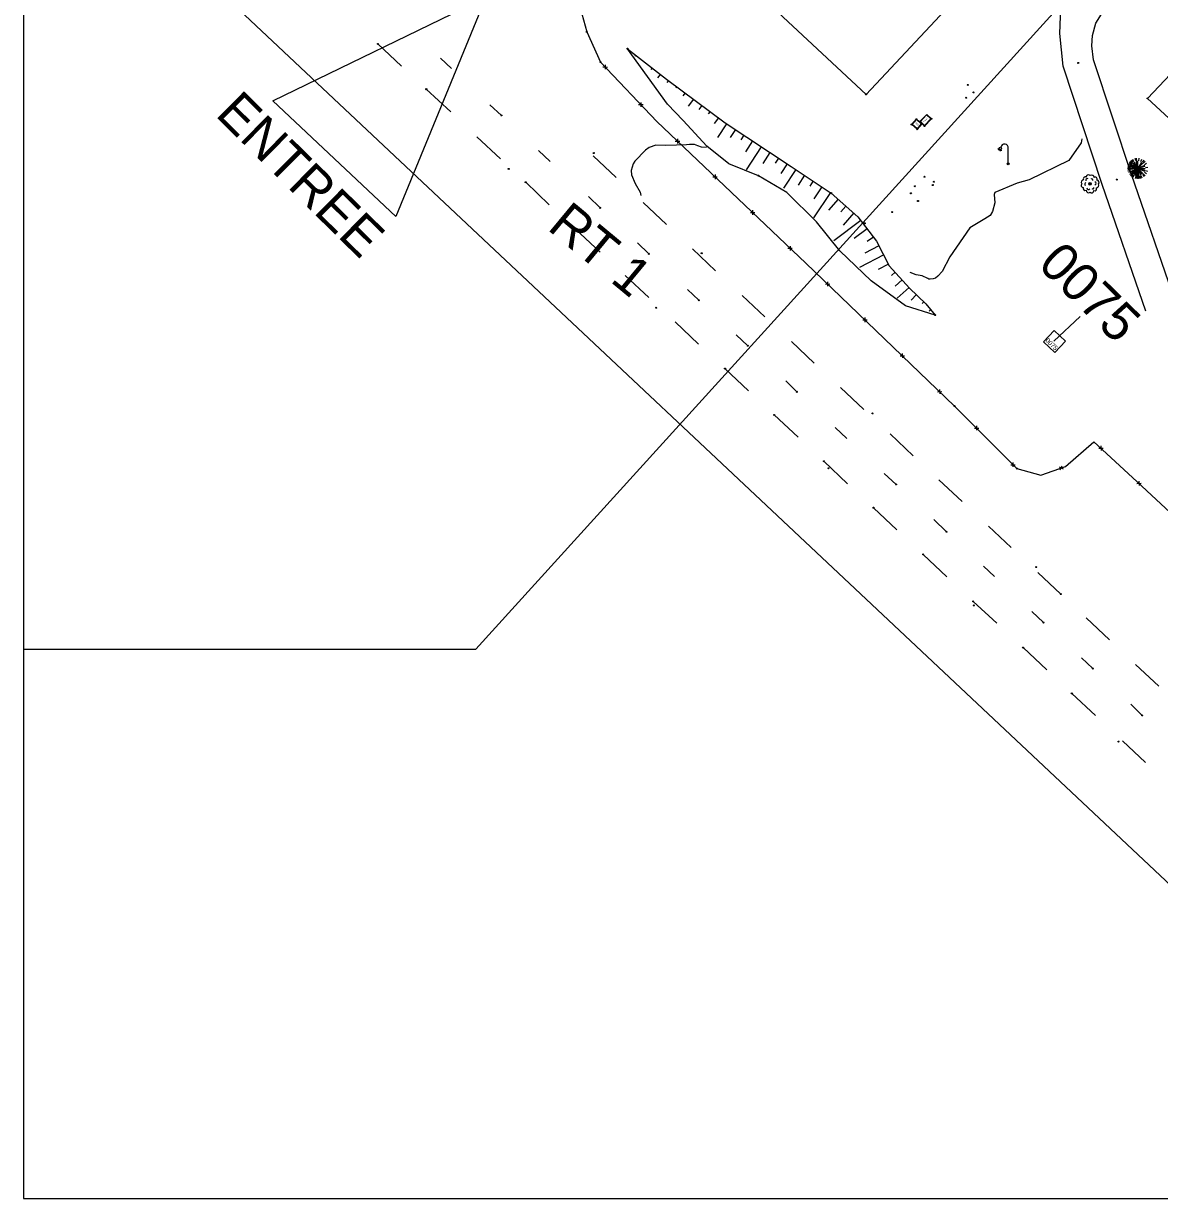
# Model space of a CAD drawing. Extents: x 344013 to 344423, y 298505 to 298795.
# Drawn here: x 344012.9 to 344122.6, y 298504.9 to 298618.3 of the extents above; entities that cross this region are included whole.
import ezdxf

# ---------------------------------------------------------------- set-up
doc = ezdxf.new("R2010")
doc.units = 0
for name, color, linetype in [('Default', 7, 'Continuous'), ('DH_CADRE -CARTOUCHE', 7, 'Continuous'), ('GO MUR EXTERIEUR', 7, 'Continuous'), ('IMM_VOIRIE VOIE FERREE', 7, 'Continuous'), ('PS_BOLT', 7, 'Continuous'), ('PS_CONST', 7, 'Continuous'), ('PS_DAWA', 7, 'Continuous'), ('PS_WELD', 7, 'Continuous'), ('RES_ELECTRICITE', 7, 'Continuous'), ('TOPO_COURBE NIVEAU', 7, 'Continuous'), ('TOPO_POINT', 7, 'Continuous'), ('TOPO_TALUS-TERRAIN NATUREL', 7, 'Continuous'), ('VOIRIE_BORDURE', 7, 'Continuous'), ('VOIRIE_ESPACE VERT', 7, 'Continuous')]:
    doc.layers.add(name, color=color, linetype=linetype)

# ---------------------------------------------------------------- blocks, each defined once
blk = doc.blocks.new('RES_ELECTRICITE')
at = {"layer": 'RES_ELECTRICITE'}
for points in [[(0, 0), (0, 1), (1, 1), (1, 0)], [(0.05, 0.05), (0.05, 0.95), (0.95, 0.95), (0.95, 0.05)]]:
    blk.add_lwpolyline(points, close=True, dxfattribs=at)
blk.add_text('EEC', height=0.2, dxfattribs=at).set_placement((0.24, 0.46))
blk = doc.blocks.new('EDF1')
at = {"layer": 'Default'}
for points in [[(-0.86, 1.46), (-0.98, 1.37)], [(-0.83, 1.42), (-0.93, 1.3)], [(-0.79, 1.4), (-0.86, 1.26)], [(-0.75, 1.39), (-0.78, 1.23)], [(-0.7, 1.4), (-0.68, 1.24)], [(0, 0.1), (0, 1.5)]]:
    blk.add_lwpolyline(points, dxfattribs=at)
for centre, radius in [((-0.75, 1.5), 0.112), ((0, 0), 0.1)]:
    blk.add_circle(centre, radius, dxfattribs=at)
blk.add_arc((-0.35, 1.55), 0.354, 351.8699, 171.8699, dxfattribs=at)
blk = doc.blocks.new('POINT_DISPLAY')
at = {"layer": 'Default'}
blk.add_circle((0, 0), 0.05, dxfattribs=at)
blk = doc.blocks.new('ARB1')
at = {"layer": 'Default'}
blk.add_circle((0, 0), 0.122, dxfattribs=at)
for centre, radius, start, end in [((-0.61, 0.14), 0.241, 88.4583, 215.1928), ((-0.47, 0.5), 0.183, 53.9554, 222.2066), ((-0.37, -0.02), 0.149, 103.7092, 242.3465), ((-0.28, 0.37), 0.134, 52.4396, 209.5496), ((-0.15, 0.66), 0.211, 43.6925, 183.5969), ((0.14, 0.61), 0.241, 358.4583, 125.1928), ((0.16, 0.38), 0.112, 330.5895, 133.7127), ((0.5, 0.47), 0.183, 325.1444, 131.0175), ((0.46, 0.05), 0.137, 276.6214, 88.967), ((0.61, -0.14), 0.241, 268.4583, 35.1928), ((0.66, 0.15), 0.211, 313.6925, 93.5969), ((-0.66, -0.15), 0.211, 133.6925, 273.5969), ((-0.48, -0.44), 0.19, 155.2243, 300.9377), ((-0.14, -0.61), 0.241, 178.4583, 305.1928), ((-0.16, -0.42), 0.148, 159.5371, 338.1663), ((0.15, -0.66), 0.211, 223.6925, 3.5969), ((0.27, -0.38), 0.112, 210.5895, 13.7127), ((0.45, -0.48), 0.188, 243.1323, 33.0297)]:
    blk.add_arc(centre, radius, start, end, dxfattribs=at)
blk = doc.blocks.new('ARB2')
at = {"layer": 'Default'}
for p, q in [((-0.73, 0), (-0.98, 0)), ((-0.72, 0.1), (-0.97, 0.13)), ((-0.71, 0.2), (-0.94, 0.26)), ((-0.67, 0.29), (-0.9, 0.38)), ((-0.63, 0.37), (-0.84, 0.5)), ((-0.58, 0.45), (-0.78, 0.6)), ((-0.51, 0.53), (-0.69, 0.7)), ((-0.44, 0.59), (-0.59, 0.79)), ((-0.36, 0.64), (-0.48, 0.86)), ((-0.18, 0.72), (-0.24, 0.96)), ((-0.09, 0.74), (-0.12, 0.98)), ((0.11, 0.74), (0.14, 0.98)), ((0.29, 0.68), (0.39, 0.91)), ((0.46, 0.59), (0.61, 0.79)), ((0.53, 0.53), (0.71, 0.7)), ((0.65, 0.37), (0.86, 0.5)), ((0.74, 0.1), (0.99, 0.13)), ((-0.72, -0.1), (-0.97, -0.13)), ((-0.71, -0.2), (-0.94, -0.26)), ((-0.67, -0.29), (-0.9, -0.38)), ((-0.58, -0.45), (-0.78, -0.6)), ((-0.51, -0.53), (-0.69, -0.7)), ((-0.44, -0.59), (-0.59, -0.79)), ((-0.36, -0.64), (-0.48, -0.86)), ((-0.18, -0.72), (-0.24, -0.96)), ((-0.09, -0.74), (-0.12, -0.98)), ((0.01, -0.74), (0.01, -0.99)), ((0.11, -0.74), (0.14, -0.98)), ((0.2, -0.72), (0.26, -0.96)), ((0.29, -0.69), (0.39, -0.92)), ((0.46, -0.59), (0.61, -0.79)), ((0.53, -0.53), (0.71, -0.7)), ((0.65, -0.37), (0.86, -0.5)), ((0.72, -0.2), (0.96, -0.26))]:
    blk.add_line(p, q, dxfattribs=at)
for points in [[(-0.69, 0.09), (0.01, 0), (-0.34, 0.61)], [(-0.49, -0.5), (0.01, 0), (-0.69, 0)], [(-0.64, -0.27), (0.01, 0), (-0.69, -0.09)], [(-0.49, 0.5), (0.01, 0), (-0.67, 0.18)], [(-0.42, 0.56), (0.01, 0), (-0.64, 0.27)], [(-0.17, 0.68), (0.01, 0), (-0.6, 0.35)], [(-0.17, -0.68), (0.01, 0), (-0.6, -0.35)], [(-0.54, -0.43), (0.01, 0), (-0.34, -0.61)], [(-0.08, -0.7), (0.01, 0), (-0.42, -0.56)], [(0.01, 0.01), (0.01, 0), (-0.08, 0.7)], [(0.01, -0.7), (0.01, 0), (0, 0)], [(0.36, 0.61), (0.01, 0), (0.01, 0.7)], [(0.66, 0.27), (0.01, 0), (0.51, 0.5)], [(0.69, 0.18), (0.01, 0), (0.71, 0)], [(0.44, -0.56), (0.01, 0), (0.66, -0.27)], [(0.51, -0.5), (0.01, 0), (0.69, -0.18)], [(0.1, -0.7), (0.01, 0), (0.28, -0.65)], [(0.02, 0), (0.01, 0), (0.01, -0.01)]]:
    blk.add_lwpolyline(points, dxfattribs=at)

msp = doc.modelspace()

# ---------------------------------------------------------------- linework, layer by layer
at = {"layer": 'DH_CADRE -CARTOUCHE'}
for points in [[(344012.91, 298504.88), (344422.91, 298504.88), (344422.91, 298791.88), (344012.91, 298791.88)], [(344113.5, 298587.61), (344112.41, 298588.64), (344111.38, 298587.55), (344112.47, 298586.52)]]:
    msp.add_lwpolyline(points, close=True, dxfattribs=at)
msp.add_lwpolyline([(344092.72, 298634.81), (344105.19, 298623.15), (344094.24, 298611.44), (344080.1, 298624.66), (344082.36, 298627.12), (344084.04, 298625.58), (344092.72, 298634.81)], dxfattribs=at)
at = {"layer": 'GO MUR EXTERIEUR'}
for points in [[(344092.72, 298634.81), (344105.19, 298623.15), (344094.24, 298611.44), (344080.1, 298624.66), (344082.36, 298627.12), (344084.04, 298625.58)], [(344036.98, 298610.8), (344057.54, 298620.81), (344048.84, 298599.66)]]:
    msp.add_lwpolyline(points, close=True, dxfattribs=at)
at = {"layer": 'IMM_VOIRIE VOIE FERREE'}
for points in [[(344047.12, 298616.31), (344049.39, 298614.15)], [(344054.22, 298613.94), (344053.16, 298614.92)], [(344051.79, 298611.94), (344054.15, 298609.75)], [(344059.04, 298609.41), (344057.93, 298610.43)], [(344056.67, 298607.35), (344058.95, 298605.23)], [(344063.76, 298604.96), (344062.62, 298606.03)], [(344070.12, 298603.4), (344067.9, 298605.51)], [(344061.38, 298602.96), (344063.66, 298600.78)], [(344068.56, 298600.49), (344067.43, 298601.57)], [(344074.96, 298598.89), (344072.72, 298601)], [(344066.19, 298598.43), (344068.56, 298596.22)], [(344073.27, 298596.05), (344072.18, 298597.11)], [(344079.7, 298594.42), (344077.49, 298596.53)], [(344070.99, 298593.96), (344073.28, 298591.82)], [(344078.09, 298591.57), (344076.99, 298592.6)], [(344084.46, 298589.96), (344082.27, 298592.04)], [(344075.8, 298589.5), (344078.06, 298587.34)], [(344082.82, 298587.18), (344081.7, 298588.24)], [(344089.22, 298585.5), (344087.04, 298587.58)], [(344080.62, 298584.97), (344082.88, 298582.83)], [(344087.55, 298582.73), (344086.49, 298583.78)], [(344094.01, 298581.04), (344091.78, 298583.16)], [(344085.36, 298580.5), (344087.68, 298578.35)], [(344092.38, 298578.22), (344091.26, 298579.28)], [(344098.79, 298576.56), (344096.56, 298578.67)], [(344090.17, 298576.03), (344092.44, 298573.86)], [(344097.14, 298573.79), (344096, 298574.84)], [(344103.53, 298572.13), (344101.27, 298574.23)], [(344094.95, 298571.55), (344097.21, 298569.4)], [(344102.01, 298569.22), (344100.77, 298570.4)], [(344108.26, 298567.71), (344106.06, 298569.78)], [(344099.76, 298567.04), (344102.04, 298564.87)], [(344106.63, 298564.9), (344105.57, 298565.91)], [(344113.04, 298563.21), (344110.82, 298565.29)], [(344104.58, 298562.5), (344106.86, 298560.4)], [(344111.37, 298560.46), (344110.25, 298561.52)], [(344117.74, 298558.8), (344115.49, 298560.91)], [(344109.39, 298558.04), (344111.68, 298555.9)], [(344116.13, 298556.02), (344115.03, 298557.06)], [(344122.51, 298554.31), (344120.26, 298556.42)], [(344114.1, 298553.63), (344116.38, 298551.48)], [(344120.9, 298551.5), (344119.8, 298552.57)], [(344118.99, 298549.05), (344121.21, 298546.95)]]:
    msp.add_lwpolyline(points, dxfattribs=at)
at = {"layer": 'PS_BOLT'}
msp.add_lwpolyline([(344173.44, 298593.64), (344172.43, 298592.57), (344178.46, 298586.94), (344174.4, 298582.59), (344168.38, 298588.23), (344167.09, 298586.85), (344168.39, 298585.59), (344159.32, 298576.07), (344121.41, 298611.05), (344130.72, 298620.94), (344149.46, 298603.38), (344147.72, 298601.52)], dxfattribs=at)
at = {"layer": 'PS_CONST'}
msp.add_line((344112.35, 298587.62), (344114.92, 298590.01), dxfattribs=at)
msp.add_lwpolyline([(344012.91, 298557.89), (344056.56, 298557.89), (344121.14, 298629.06)], dxfattribs=at)
at = {"layer": 'PS_DAWA'}
msp.add_lwpolyline([(344017.68, 298634.73), (344131.74, 298527.49)], dxfattribs=at)
at = {"layer": 'PS_WELD'}
for p, q in [((344068.84, 298614.09), (344069.27, 298614.08)), ((344069.06, 298614.29), (344069.05, 298613.87)), ((344072.28, 298610.46), (344072.71, 298610.45)), ((344072.5, 298610.67), (344072.49, 298610.24)), ((344075.82, 298606.92), (344076.25, 298606.93)), ((344076.03, 298607.14), (344076.04, 298606.71)), ((344079.45, 298603.48), (344079.87, 298603.49)), ((344079.66, 298603.69), (344079.67, 298603.27)), ((344083.07, 298600.03), (344083.5, 298600.04)), ((344083.28, 298600.25), (344083.29, 298599.82)), ((344086.7, 298596.59), (344087.12, 298596.6)), ((344086.9, 298596.8), (344086.91, 298596.38)), ((344090.31, 298593.13), (344090.73, 298593.14)), ((344090.52, 298593.35), (344090.53, 298592.92)), ((344093.92, 298589.67), (344094.34, 298589.68)), ((344094.12, 298589.89), (344094.13, 298589.46)), ((344097.52, 298586.21), (344097.95, 298586.21)), ((344097.73, 298586.42), (344097.74, 298586)), ((344101.34, 298582.96), (344101.35, 298582.53)), ((344101.13, 298582.74), (344101.55, 298582.75)), ((344104.9, 298579.45), (344104.9, 298579.02)), ((344104.69, 298579.23), (344105.11, 298579.23)), ((344116.7, 298577.29), (344117.13, 298577.3)), ((344116.91, 298577.51), (344116.92, 298577.08)), ((344108.21, 298575.69), (344108.64, 298575.69)), ((344108.42, 298575.9), (344108.42, 298575.48)), ((344112.88, 298575.48), (344113.26, 298575.29)), ((344112.98, 298575.2), (344113.16, 298575.58)), ((344120.37, 298573.89), (344120.79, 298573.9)), ((344120.57, 298574.11), (344120.59, 298573.68))]:
    msp.add_line(p, q, dxfattribs=at)
msp.add_lwpolyline([(344066.32, 298620.99), (344067.28, 298617.46), (344068.6, 298614.56), (344074.05, 298608.81), (344088.41, 298595.16), (344102.78, 298581.36), (344108.79, 298575.32), (344111.12, 298574.7), (344113.48, 298575.53), (344116.24, 298577.92), (344119.96, 298574.47), (344130.45, 298564.7)], dxfattribs=at)
at = {"layer": 'TOPO_COURBE NIVEAU'}
for points in [[(344078.82, 298606.3), (344078.34, 298606.35), (344078.01, 298606.48), (344077.67, 298606.61), (344077.21, 298606.61), (344076.9, 298606.58), (344075.94, 298606.55), (344074.91, 298606.51), (344073.95, 298606.53), (344073.31, 298606.3), (344072.95, 298606.06), (344071.91, 298604.98), (344071.77, 298604.74), (344071.55, 298604.08), (344071.61, 298603.68), (344071.96, 298602.85), (344072.43, 298602.01), (344072.51, 298601.69)], [(344115.05, 298607.16), (344115.01, 298606.77), (344113.82, 298605.07), (344109.98, 298603.19), (344108.82, 298602.87), (344106.67, 298601.96), (344106.6, 298601.78), (344106.66, 298600.97), (344106.44, 298600.12), (344106.21, 298599.76), (344105.69, 298599.44), (344104.27, 298598.55), (344102.32, 298595.76), (344101.57, 298594.35), (344101.18, 298593.89), (344100.95, 298593.7), (344100.7, 298593.65), (344100.42, 298593.6), (344100.31, 298593.6), (344100.19, 298593.66), (344099.64, 298593.92), (344099.07, 298594.02), (344098.49, 298594.26)]]:
    msp.add_lwpolyline(points, dxfattribs=at)
at = {"layer": 'TOPO_TALUS-TERRAIN NATUREL'}
for p, q in [((344072.01, 298615.23), (344071.93, 298615.12)), ((344072.8, 298614.62), (344072.75, 298614.55)), ((344073.59, 298614.01), (344073.47, 298613.85)), ((344074.38, 298613.39), (344074.1, 298613.03)), ((344075.17, 298612.78), (344075.01, 298612.57)), ((344075.97, 298612.18), (344075.88, 298612.06)), ((344076.77, 298611.58), (344076.56, 298611.29)), ((344077.58, 298610.98), (344077.07, 298610.3)), ((344078.38, 298610.38), (344078.08, 298609.99)), ((344079.18, 298609.78), (344079, 298609.55)), ((344079.98, 298609.18), (344079.57, 298608.64)), ((344080.78, 298608.59), (344079.91, 298607.27)), ((344081.62, 298608.04), (344081.11, 298607.27)), ((344082.45, 298607.49), (344082.16, 298607.04)), ((344083.29, 298606.94), (344082.59, 298605.88)), ((344084.12, 298606.39), (344082.65, 298604.16)), ((344084.96, 298605.84), (344084.26, 298604.78)), ((344085.79, 298605.29), (344085.46, 298604.79)), ((344086.63, 298604.74), (344086, 298603.79)), ((344087.46, 298604.19), (344086.27, 298602.39)), ((344088.3, 298603.63), (344087.67, 298602.69)), ((344089.13, 298603.08), (344088.8, 298602.58)), ((344089.96, 298602.52), (344089.19, 298601.36)), ((344090.8, 298601.97), (344089.16, 298599.52)), ((344091.55, 298601.32), (344090.62, 298600.27)), ((344092.3, 298600.65), (344091.81, 298600.1)), ((344093.05, 298599.99), (344092.02, 298598.83)), ((344093.73, 298599.26), (344091.13, 298597.3)), ((344094.33, 298598.47), (344093.1, 298597.53)), ((344094.94, 298597.67), (344094.35, 298597.23)), ((344095.47, 298596.83), (344094.11, 298596.11)), ((344095.94, 298595.94), (344093.61, 298594.72)), ((344096.4, 298595.06), (344095.41, 298594.53)), ((344097.04, 298594.29), (344096.69, 298593.97)), ((344097.71, 298593.55), (344097.04, 298592.94)), ((344098.39, 298592.81), (344097.24, 298591.77)), ((344099.1, 298592.11), (344098.58, 298591.58)), ((344099.81, 298591.41), (344099.65, 298591.24)), ((344100.47, 298590.66), (344100.32, 298590.53))]:
    msp.add_line(p, q, dxfattribs=at)
for points in [[(344071.22, 298615.85), (344074.99, 298612.91), (344080.63, 298608.7), (344087, 298604.49), (344090.87, 298601.92), (344093.45, 298599.63), (344095.24, 298597.27), (344096.48, 298594.9), (344098.44, 298592.75), (344100, 298591.22), (344100.91, 298590.14)], [(344100.91, 298590.14), (344098.03, 298591.04), (344094.73, 298593.43), (344091.71, 298596.35), (344089.45, 298599.15), (344086.59, 298601.97), (344083.86, 298603.59), (344080.98, 298604.75), (344078.86, 298606.45), (344076.59, 298608.92), (344075.06, 298610.5), (344071.22, 298615.85)]]:
    msp.add_lwpolyline(points, dxfattribs=at)
at = {"layer": 'VOIRIE_BORDURE'}
for points in [[(344121.25, 298590.51), (344117.02, 298602.74), (344113.25, 298614.16), (344112.94, 298617.3), (344113.04, 298619.78), (344112.78, 298622.83), (344112.21, 298626.55), (344111.4, 298629.95)], [(344124.09, 298591.49), (344119.86, 298603.7), (344116.2, 298614.78), (344116.04, 298616.13), (344116.1, 298617.11), (344116.41, 298618.32), (344117.14, 298619.44), (344117.99, 298620.37), (344118.92, 298621.17), (344120.41, 298621.95)]]:
    msp.add_lwpolyline(points, dxfattribs=at)

# ---------------------------------------------------------------- block references
at = {"layer": 'RES_ELECTRICITE'}
for p, xscale, yscale, rotation in [((344098.64, 298608.53), 0.6898693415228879, 0.690076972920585, -41.04656495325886), ((344099.87, 298608.38), 0.969343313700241, 0.6171012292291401, 46.150708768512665)]:
    msp.add_blockref('RES_ELECTRICITE', p, dxfattribs=dict(at, xscale=xscale, yscale=yscale, rotation=rotation))
msp.add_blockref('EDF1', (344107.95, 298604.74), dxfattribs=at)
at = {"layer": 'TOPO_POINT'}
for p in [(344067.28, 298617.46), (344047.12, 298616.31), (344071.22, 298615.85), (344068.6, 298614.56), (344114.72, 298614.47), (344104.05, 298612.35), (344051.79, 298611.94), (344094.24, 298611.44), (344103.91, 298611.11), (344104.62, 298611.63), (344121.41, 298611.05), (344059.04, 298609.41), (344099.1, 298609.04), (344099.43, 298608.81), (344100.54, 298609.08), (344098.64, 298608.53), (344099.16, 298608.07), (344099.87, 298608.38), (344067.95, 298605.78), (344107.95, 298604.74), (344120.46, 298604.29), (344059.74, 298604.25), (344083.86, 298603.59), (344099.88, 298603.49), (344118.44, 298603.22), (344061.38, 298602.96), (344098.95, 298602.57), (344100.67, 298602.69), (344100.79, 298603), (344115.86, 298602.8), (344090.87, 298601.92), (344098.57, 298601.89), (344099.25, 298601.15), (344068.56, 298600.49), (344096.77, 298600.08), (344094.1, 298598.99), (344066.19, 298598.43), (344073.27, 298596.05), (344078.37, 298596.11), (344073.98, 298590.84), (344078.09, 298591.57), (344100.91, 298590.14), (344082.82, 298587.18), (344080.62, 298584.97), (344087.55, 298582.73), (344085.36, 298580.5), (344094.87, 298580.65), (344102.78, 298581.36), (344090.17, 298576.03), (344090.62, 298575.35), (344108.79, 298575.32), (344097.14, 298573.79), (344094.95, 298571.55), (344102.01, 298569.22), (344099.76, 298567.04), (344110.66, 298565.81), (344104.58, 298562.5), (344113.04, 298563.21), (344104.64, 298562.12), (344111.37, 298560.46), (344109.39, 298558.04), (344116.13, 298556.02), (344114.1, 298553.63), (344120.9, 298551.5), (344118.61, 298548.98)]:
    msp.add_blockref('POINT_DISPLAY', p, dxfattribs=at)
at = {"layer": 'VOIRIE_ESPACE VERT'}
for name, p in [('ARB2', (344120.46, 298604.29)), ('ARB1', (344115.86, 298602.8))]:
    msp.add_blockref(name, p, dxfattribs=at)

# ---------------------------------------------------------------- texts
at = {"layer": 'PS_CONST'}
for s, height, rotation, p in [('ENTREE', 3.662, 315.3665, (344031.33, 298609.41)), ('RT 1', 3.662, 320.3665, (344063.37, 298598.46)), ('0075', 3.662, 315.3665, (344110.7, 298594.89)), ('0075', 0.445, 315.3665, (344111.51, 298587.65))]:
    msp.add_text(s, height=height, rotation=rotation, dxfattribs=at).set_placement(p)

doc.saveas('drawing.dxf')
